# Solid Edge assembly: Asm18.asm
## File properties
Author: Mac
Template: Normal.asm
Last saved by: Mac
Revision: 73
Application: Solid Edge
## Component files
paat3.par
kajut1.4.par
esiklaas1.par
kylgklaas.par
dek_klaas1.par
dek_klaas1_mir.par
kylgklaas_mir.par
jalg2.asm
bowthruster.asm
naidiku_paneel.par
dashboard.par
sisetrepp.par
raam.asm
reeling2.1_mir.par
Kabiiniuks.asm
luuk.asm
mootor.par
tekk10.par
voori luuk.par
aken.par
paak.par
varikatus2.par
rool.asm
redel.par
tool.par
flybridge_luuk.par
reeling2.1.par
targa.par
sild.par
pukspriit.par
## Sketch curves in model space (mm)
spline (-15.6149, 28.1976, 10.4) -> (-35.3416, 28.6548, 10.4) -> (-56.5788, 28.6594, 10.4)
line (-56.5788, 28.6594, 10.4) -> (-56.5788, 0, 10.4)
line (-56.5788, 0, 10.4) -> (40.9981, 0, 10.4)
spline (40.9981, 0, 10.4) -> (38.6867, 11.8943, 10.4) -> (32.9245, 24.3434, 10.4)
spline (32.9245, 24.3434, 10.4) -> (10.2391, 26.7379, 10.4) -> (-15.6149, 28.1976, 10.4)
line (-116.2695, 0, -19.4214) -> (97.8945, 0, -34.3972)
line (-26.4896, 0, 51.5668) -> (-26.4896, 0, -55.0575)
line (-110.4896, 0, -13.1711) -> (-110.4896, 0, -5.1035)
arc centre (-55.2976, 0, -24.6295) radius 56.3688 from (-110.0363, 0, -11.1711) through (-110.272, 0, -12.169) to (-110.4896, 0, -13.1711)
arc centre (18.3803, 0.3808, 0) radius 124.3034 from (-103.6585, 24, 0) through (-103.2338, 26.0978, 0) to (-102.7729, 28.1879, 0)
arc centre (-94.797, 27.5681, 0) radius 8 from (-102.7729, 28.1879, 0) through (-100.1758, 33.49, 0) to (-95.1142, 35.5618, 0)
spline (-95.1142, 35.5618, 0) -> (30.0728, 32.6689, 0) -> (106.0979, 0.5496, 0)
arc centre (105.0005, 0, 0) radius 1.2274 from (106.0979, 0.5496, 0) through (106.1949, 0.2824, 0) to (106.2279, 0, 0)
line (106.2279, 0, 0) -> (-99.6166, 0, 0)
line (-99.6166, 24, 0) -> (-99.6166, 0, 0)
line (-99.6166, 24, 0) -> (-103.6585, 24, 0)
line (-100.2896, 0.5, -11.1711) -> (-100.2896, 24, -11.1711)
line (-100.2896, 24, -11.1711) -> (-100.2896, 24, -0.2)
arc centre (18.0065, 0.4994, 0) radius 123.0059 from (-101.6038, 29.2016, 0) through (-104.1475, 14.9509, 0) to (-104.9994, 0.5, 0)
spline (-104.9994, 0.5, 0) -> (-110.542, 0.5, -13.4256) -> (-112.3877, 0.5, -36.2684)
spline (-110.7878, 30.7782, -24.5324) -> (-28.564, 29.4368, -24.5324) -> (52.4813, 16.4919, -24.5324)
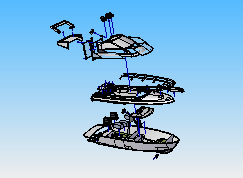
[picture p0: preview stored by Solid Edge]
